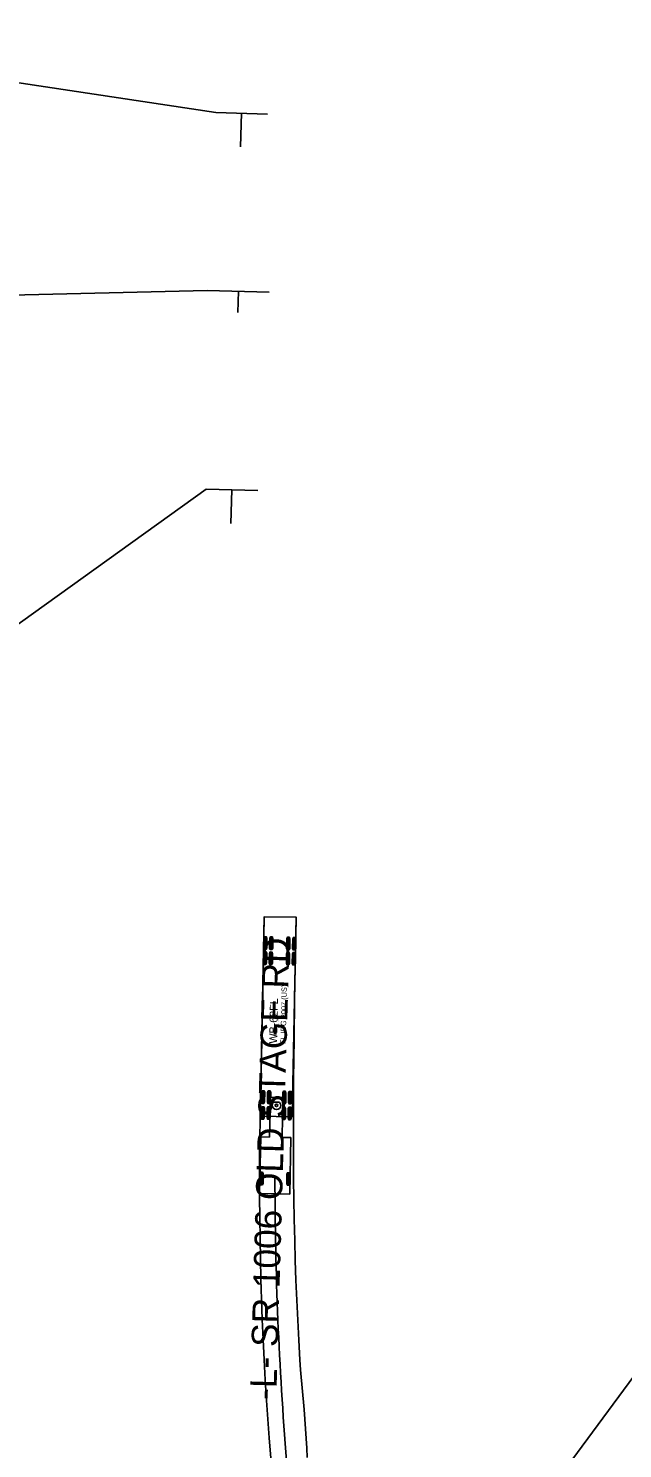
# Model space of a CAD drawing. Extents: x 2096670 to 2098561, y 684033 to 689893.
# Drawn here: x 2097615 to 2097772.9, y 686268.1 to 686645.1 of the extents above; entities that cross this region are included whole.
import ezdxf

# ---------------------------------------------------------------- set-up
doc = ezdxf.new("R2010")
doc.units = 0
for name, color, linetype in [('Default', 7, 'Continuous'), ('Exist Sign E Chevron Left', 7, 'Continuous'), ('Exist Support 1', 7, 'Continuous'), ('Old_Level_63', 7, 'Continuous'), ('Prop DSN Text', 7, 'Continuous'), ('Prop Sign E Left Lane Must Turn Left CELL', 7, 'Continuous')]:
    doc.layers.add(name, color=color, linetype=linetype)

msp = doc.modelspace()

# ---------------------------------------------------------------- linework, layer by layer
at = {"layer": 'Default'}
for p, q in [((2097516.49, 686645.13), (2097664.79, 686622.79)), ((2097473.27, 686387.28), (2097662.2, 686522.83))]:
    msp.add_line(p, q, dxfattribs=at)
at = {"layer": 'Exist Sign E Chevron Left'}
msp.add_line((2097707.06, 686194.24), (2097832.92, 686364.65), dxfattribs=at)
at = {"layer": 'Exist Support 1'}
for p, q in [((2097662.52, 686575.58), (2097678.97, 686575.11)), ((2097670.81, 686575.34), (2097670.65, 686569.75))]:
    msp.add_line(p, q, dxfattribs=at)
at = {"layer": 'Old_Level_63'}
for p, q in [((2097677.69, 686409.31), (2097676.61, 686356.32)), ((2097686.19, 686409.14), (2097677.69, 686409.31)), ((2097685.1, 686356.15), (2097686.19, 686409.14)), ((2097677.72, 686400.64), (2097677.79, 686403.97)), ((2097677.93, 686400.64), (2097678, 686403.97)), ((2097678.14, 686400.63), (2097678.21, 686403.97)), ((2097679.29, 686400.61), (2097679.36, 686403.94)), ((2097679.5, 686400.61), (2097679.56, 686403.94)), ((2097679.7, 686400.6), (2097679.77, 686403.93)), ((2097683.82, 686400.52), (2097683.89, 686403.85)), ((2097684.03, 686400.51), (2097684.1, 686403.85)), ((2097684.24, 686400.51), (2097684.3, 686403.84)), ((2097685.39, 686400.48), (2097685.45, 686403.82)), ((2097685.59, 686400.48), (2097685.66, 686403.81)), ((2097685.8, 686400.48), (2097685.87, 686403.81)), ((2097677.64, 686396.64), (2097677.71, 686399.97)), ((2097677.85, 686396.64), (2097677.92, 686399.97)), ((2097678.06, 686396.63), (2097678.12, 686399.97)), ((2097679.21, 686396.61), (2097679.27, 686399.94)), ((2097679.41, 686396.61), (2097679.48, 686399.94)), ((2097679.62, 686396.6), (2097679.69, 686399.93)), ((2097683.74, 686396.52), (2097683.81, 686399.85)), ((2097683.95, 686396.51), (2097684.01, 686399.85)), ((2097684.15, 686396.51), (2097684.22, 686399.84)), ((2097685.3, 686396.49), (2097685.37, 686399.82)), ((2097685.51, 686396.48), (2097685.58, 686399.81)), ((2097685.72, 686396.48), (2097685.79, 686399.81)), ((2097677.13, 686359.74), (2097677.2, 686363.08)), ((2097677.34, 686359.74), (2097677.41, 686363.07)), ((2097677.55, 686359.74), (2097677.62, 686363.07)), ((2097678.7, 686359.71), (2097678.77, 686363.05)), ((2097678.91, 686359.71), (2097678.98, 686363.04)), ((2097679.12, 686359.7), (2097679.19, 686363.04)), ((2097682.73, 686359.63), (2097682.8, 686362.96)), ((2097682.94, 686359.63), (2097683.01, 686362.96)), ((2097683.15, 686359.62), (2097683.22, 686362.95)), ((2097684.3, 686359.6), (2097684.37, 686362.93)), ((2097684.51, 686359.59), (2097684.58, 686362.93)), ((2097684.72, 686359.59), (2097684.78, 686362.92)), ((2097677.05, 686355.55), (2097677.12, 686358.88)), ((2097677.26, 686355.54), (2097677.33, 686358.87)), ((2097679.29, 686361.37), (2097679.08, 686350.77)), ((2097682.63, 686361.3), (2097679.29, 686361.37)), ((2097681.74, 686360.03), (2097680.13, 686360.06)), ((2097682.41, 686350.7), (2097682.63, 686361.3)), ((2097676.61, 686356.32), (2097685.1, 686356.15)), ((2097677.47, 686355.54), (2097677.53, 686358.87)), ((2097678.62, 686355.51), (2097678.68, 686358.85)), ((2097678.82, 686355.51), (2097678.89, 686358.84)), ((2097679.03, 686355.51), (2097679.1, 686358.84)), ((2097682.65, 686355.43), (2097682.72, 686358.76)), ((2097682.86, 686355.43), (2097682.92, 686358.76)), ((2097683.06, 686355.42), (2097683.13, 686358.76)), ((2097684.21, 686355.4), (2097684.28, 686358.73)), ((2097684.42, 686355.4), (2097684.49, 686358.73)), ((2097684.63, 686355.39), (2097684.7, 686358.72)), ((2097685.1, 686356.15), (2097685.1, 686356.15)), ((2097676.74, 686350.82), (2097676.44, 686335.82)), ((2097679.08, 686350.77), (2097676.74, 686350.82)), ((2097684.74, 686350.65), (2097682.41, 686350.7)), ((2097684.44, 686335.66), (2097684.74, 686350.65)), ((2097676.73, 686338.14), (2097676.73, 686341.47)), ((2097676.94, 686338.14), (2097676.93, 686341.47)), ((2097677.14, 686338.14), (2097677.14, 686341.47)), ((2097683.89, 686338.01), (2097683.89, 686341.34)), ((2097684.1, 686338.01), (2097684.1, 686341.34)), ((2097684.31, 686338.01), (2097684.31, 686341.34)), ((2097676.44, 686335.82), (2097684.44, 686335.66)), ((2097684.44, 686335.66), (2097684.44, 686335.66))]:
    msp.add_line(p, q, dxfattribs=at)
for points in [[(2097679.8, 686261.3), (2097679.01, 686270.92), (2097678.62, 686275.87), (2097678.27, 686280.89), (2097677.94, 686286.35), (2097677.65, 686291.7), (2097677.39, 686297.05), (2097677.16, 686302.4), (2097676.96, 686307.74), (2097676.79, 686313.09), (2097676.65, 686318.44), (2097676.55, 686323.79), (2097676.47, 686329.48), (2097676.43, 686334.83), (2097676.43, 686340.18), (2097676.45, 686345.54), (2097676.51, 686350.89), (2097677.35, 686393.31), (2097677.69, 686409.31), (2097686.19, 686409.14), (2097686.18, 686408.86), (2097686.18, 686408.86)], [(2097686.18, 686408.86), (2097685.75, 686387.48), (2097685.58, 686376.83), (2097685.45, 686366.19), (2097685.4, 686355.56), (2097685.4, 686350.24), (2097685.43, 686344.93), (2097685.48, 686339.61), (2097685.55, 686334.3), (2097685.64, 686328.99), (2097685.77, 686323.36), (2097685.92, 686318.06), (2097686.1, 686312.77), (2097686.31, 686307.48), (2097686.56, 686302.2), (2097686.84, 686296.92), (2097687.17, 686291.64), (2097687.34, 686289.01), (2097688.27, 686278.43), (2097688.67, 686273.34), (2097688.84, 686270.79), (2097688.98, 686268.25), (2097689.1, 686265.71)]]:
    msp.add_lwpolyline(points, dxfattribs=at)
for points in [[(2097678.19, 686400.63), (2097677.67, 686400.64), (2097677.52, 686401.11), (2097677.57, 686403.51), (2097677.74, 686403.98), (2097678.26, 686403.96), (2097678.4, 686403.49), (2097678.35, 686401.1)], [(2097679.76, 686400.6), (2097679.24, 686400.61), (2097679.09, 686401.08), (2097679.14, 686403.48), (2097679.3, 686403.94), (2097679.82, 686403.93), (2097679.97, 686403.46), (2097679.92, 686401.06)], [(2097684.29, 686400.51), (2097683.77, 686400.52), (2097683.62, 686400.99), (2097683.67, 686403.39), (2097683.84, 686403.85), (2097684.36, 686403.84), (2097684.5, 686403.37), (2097684.45, 686400.97)], [(2097685.85, 686400.48), (2097685.33, 686400.49), (2097685.19, 686400.96), (2097685.24, 686403.36), (2097685.4, 686403.82), (2097685.92, 686403.81), (2097686.07, 686403.34), (2097686.02, 686400.94)], [(2097678.11, 686396.63), (2097677.59, 686396.64), (2097677.44, 686397.11), (2097677.49, 686399.51), (2097677.66, 686399.98), (2097678.18, 686399.97), (2097678.32, 686399.5), (2097678.27, 686397.1)], [(2097679.67, 686396.6), (2097679.15, 686396.61), (2097679.01, 686397.08), (2097679.06, 686399.48), (2097679.22, 686399.94), (2097679.74, 686399.93), (2097679.89, 686399.46), (2097679.84, 686397.06)], [(2097684.21, 686396.51), (2097683.69, 686396.52), (2097683.54, 686396.99), (2097683.59, 686399.39), (2097683.75, 686399.85), (2097684.27, 686399.84), (2097684.42, 686399.37), (2097684.37, 686396.97)], [(2097685.77, 686396.48), (2097685.25, 686396.49), (2097685.11, 686396.96), (2097685.15, 686399.36), (2097685.32, 686399.82), (2097685.84, 686399.81), (2097685.99, 686399.34), (2097685.94, 686396.94)], [(2097677.6, 686359.74), (2097677.08, 686359.75), (2097676.94, 686360.22), (2097676.98, 686362.62), (2097677.15, 686363.08), (2097677.67, 686363.07), (2097677.82, 686362.6), (2097677.77, 686360.2)], [(2097679.17, 686359.7), (2097678.65, 686359.71), (2097678.5, 686360.18), (2097678.55, 686362.58), (2097678.72, 686363.05), (2097679.24, 686363.04), (2097679.38, 686362.57), (2097679.34, 686360.17)], [(2097683.2, 686359.62), (2097682.68, 686359.63), (2097682.53, 686360.1), (2097682.58, 686362.5), (2097682.75, 686362.96), (2097683.27, 686362.95), (2097683.42, 686362.48), (2097683.37, 686360.08)], [(2097684.77, 686359.59), (2097684.25, 686359.6), (2097684.1, 686360.07), (2097684.15, 686362.47), (2097684.32, 686362.93), (2097684.84, 686362.92), (2097684.98, 686362.45), (2097684.93, 686360.05)], [(2097677.52, 686355.54), (2097677, 686355.55), (2097676.85, 686356.02), (2097676.9, 686358.42), (2097677.07, 686358.88), (2097677.59, 686358.87), (2097677.73, 686358.4), (2097677.68, 686356)], [(2097679.08, 686355.5), (2097678.56, 686355.51), (2097678.42, 686355.98), (2097678.47, 686358.38), (2097678.63, 686358.85), (2097679.15, 686358.84), (2097679.3, 686358.37), (2097679.25, 686355.97)], [(2097683.12, 686355.42), (2097682.6, 686355.43), (2097682.45, 686355.9), (2097682.5, 686358.3), (2097682.66, 686358.77), (2097683.18, 686358.75), (2097683.33, 686358.28), (2097683.28, 686355.89)], [(2097684.68, 686355.39), (2097684.16, 686355.4), (2097684.02, 686355.87), (2097684.06, 686358.27), (2097684.23, 686358.73), (2097684.75, 686358.72), (2097684.9, 686358.25), (2097684.85, 686355.85)], [(2097677.2, 686338.14), (2097676.68, 686338.14), (2097676.52, 686338.6), (2097676.52, 686341), (2097676.67, 686341.47), (2097677.19, 686341.47), (2097677.35, 686341), (2097677.35, 686338.6)], [(2097684.36, 686338.01), (2097683.84, 686338.01), (2097683.69, 686338.47), (2097683.68, 686340.87), (2097683.84, 686341.34), (2097684.36, 686341.34), (2097684.52, 686340.87), (2097684.52, 686338.47)]]:
    msp.add_lwpolyline(points, close=True, dxfattribs=at)
for centre, radius in [((2097680.92, 686359.23), 0.34), ((2097680.52, 686339.74), 0.0417)]:
    msp.add_circle(centre, radius, dxfattribs=at)
for centre, radius, start, end in [((2097680.92, 686359.23), 1.14, 133.829, 43.829), ((2098603.68, 686340.37), 923.16, 180.03935, 184.69628)]:
    msp.add_arc(centre, radius, start, end, dxfattribs=at)
at = {"layer": 'Prop DSN Text'}
for p, q in [((2097678.56, 686622.39), (2097664.79, 686622.79)), ((2097671.62, 686622.59), (2097671.36, 686613.67)), ((2097675.96, 686522.43), (2097662.2, 686522.83)), ((2097669.03, 686522.63), (2097668.77, 686513.71))]:
    msp.add_line(p, q, dxfattribs=at)
at = {"layer": 'Prop Sign E Left Lane Must Turn Left CELL'}
msp.add_line((2097380.91, 686568.84), (2097662.52, 686575.58), dxfattribs=at)

# ---------------------------------------------------------------- texts
at = {"layer": 'Default'}
msp.add_text('-L- SR 1006 OLD STAGE RD', height=7, rotation=88.3348, dxfattribs=at).set_placement((2097680.86, 686280.96))
at = {"layer": 'Old_Level_63'}
for s, height, p in [('FL IDG 2007 (US)', 1.4167, (2097683.38, 686375.48)), ('WB-62FL', 2.125, (2097681.08, 686375.6)), ('(c) 2023 Transoft Solutions, Inc. All rights reserved.', 0.085, (2097681.4, 686380.99))]:
    msp.add_text(s, height=height, rotation=88.829, dxfattribs=at).set_placement(p)

doc.saveas('drawing.dxf')
